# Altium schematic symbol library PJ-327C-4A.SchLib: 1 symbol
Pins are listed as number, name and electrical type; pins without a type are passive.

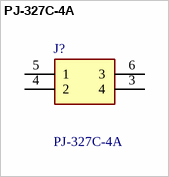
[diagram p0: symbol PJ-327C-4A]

## PJ-327C-4A
designator J?
3.5mm headphone jack 30V 500mA SMD  Audio Connectors ROHS; Manufacturer_Name: Korean Hroparts Elec; Geometry.Height: 5.9mm
footprint PJ327C4A
pins: 3 4, 4 2, 5 1, 6 3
